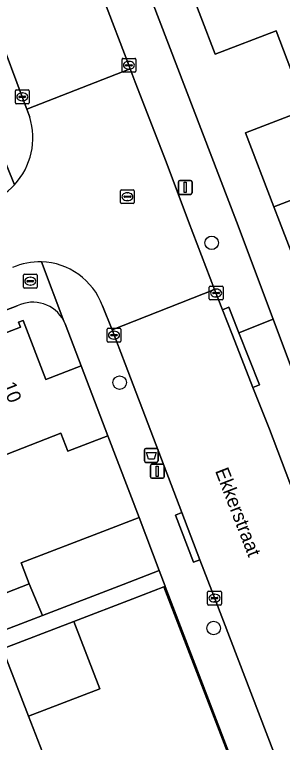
# Model space of a CAD drawing. Extents: x 159262 to 160143, y 383399 to 384319.
# Drawn here: x 159474.9 to 159494.3, y 383712.3 to 383765 of the extents above; entities that cross this region are included whole.
import ezdxf

# ---------------------------------------------------------------- set-up
doc = ezdxf.new("R2010")
doc.units = 0
for name, color, linetype in [('IMGEO_Afvalbak', 7, 'Continuous'), ('IMGEO_Boom', 7, 'Continuous'), ('IMGEO_Brandkraan', 7, 'Continuous'), ('IMGEO_Erf', 7, 'Continuous'), ('IMGEO_Kolk', 7, 'Continuous'), ('IMGEO_Lichtmast', 7, 'Continuous'), ('IMGEO_Muur', 7, 'Continuous'), ('IMGEO_Openbare_ruimte_label', 7, 'Continuous'), ('IMGEO_Pand', 7, 'Continuous'), ('IMGEO_Pand_nummerreeks', 7, 'Continuous'), ('IMGEO_Rijbaan_lokaal_gesloten', 7, 'Continuous'), ('IMGEO_Rijbaan_lokaal_open', 7, 'Continuous'), ('IMGEO_Rioolput', 7, 'Continuous'), ('IMGEO_Voetpad_open', 7, 'Continuous')]:
    doc.layers.add(name, color=color, linetype=linetype)

msp = doc.modelspace()

# ---------------------------------------------------------------- linework, layer by layer
at = {"layer": 'IMGEO_Afvalbak'}
for p, q in [((159484.342, 383732.689), (159484.342, 383733.489)), ((159484.342, 383733.489), (159484.342, 383732.689)), ((159484.442, 383733.589), (159485.232, 383733.589)), ((159485.232, 383733.589), (159484.442, 383733.589)), ((159485.332, 383733.489), (159485.332, 383732.689)), ((159485.332, 383732.689), (159485.332, 383733.489)), ((159485.232, 383732.589), (159484.442, 383732.589)), ((159484.442, 383732.589), (159485.232, 383732.589))]:
    msp.add_line(p, q, dxfattribs=at)
msp.add_lwpolyline([(159484.485, 383733.303), (159485.189, 383733.303), (159485.04, 383732.833), (159484.634, 383732.833), (159484.485, 383733.303)], dxfattribs=at)
for centre, start, end in [((159484.442, 383733.489), 90, 180), ((159484.442, 383733.489), 90, 180), ((159485.232, 383733.489), 0, 90), ((159485.232, 383733.489), 360, 90), ((159484.442, 383732.689), 180, 270), ((159484.442, 383732.689), 180, 270), ((159485.232, 383732.689), 270, 0), ((159485.232, 383732.689), 270, 0)]:
    msp.add_arc(centre, 0.1, start, end, dxfattribs=at)
at = {"layer": 'IMGEO_Boom'}
for centre in [(159489.216, 383748.468), (159482.553, 383738.358), (159489.356, 383720.608)]:
    msp.add_circle(centre, 0.489, dxfattribs=at)
at = {"layer": 'IMGEO_Brandkraan'}
for p, q in [((159475.58, 383745.266), (159475.58, 383746.118)), ((159475.655, 383746.192), (159476.507, 383746.192)), ((159476.581, 383746.118), (159476.581, 383745.266)), ((159475.839, 383745.686), (159475.839, 383745.698)), ((159476.277, 383745.649), (159475.879, 383745.649)), ((159475.882, 383745.735), (159476.28, 383745.735)), ((159476.068, 383745.972), (159476.093, 383745.972)), ((159476.323, 383745.698), (159476.323, 383745.686)), ((159476.507, 383745.192), (159475.655, 383745.192)), ((159476.091, 383745.412), (159476.066, 383745.412))]:
    msp.add_line(p, q, dxfattribs=at)
for points in [[(159475.58, 383745.266), (159475.58, 383746.118)], [(159475.655, 383746.192), (159476.507, 383746.192)], [(159476.581, 383746.118), (159476.581, 383745.266)], [(159476.507, 383745.192), (159475.655, 383745.192)]]:
    msp.add_lwpolyline(points, dxfattribs=at)
for centre, radius, start, end in [((159475.657, 383746.116), 0.0765, 91.552, 178.448), ((159475.657, 383746.116), 0.0765, 91.552, 178.448), ((159476.505, 383746.116), 0.0765, 1.552, 88.448), ((159476.505, 383746.116), 0.0765, 1.552, 88.448), ((159475.879, 383745.695), 0.0403, 85.8775, 175.7526), ((159475.876, 383745.685), 0.0366, 178.938, 274.7102), ((159476.28, 383745.692), 0.043, 264.8664, 352.4533), ((159476.284, 383745.697), 0.0386, 1.7309, 96.639), ((159475.657, 383745.268), 0.0765, 181.552, 268.448), ((159475.657, 383745.268), 0.0765, 181.552, 268.448), ((159476.505, 383745.268), 0.0765, 271.552, 358.448), ((159476.505, 383745.268), 0.0765, 271.552, 358.448)]:
    msp.add_arc(centre, radius, start, end, dxfattribs=at)
for centre, major_axis, ratio, start_param, end_param in [((159476.067, 383745.692), (-0.387, 0.002), 0.722429, 4.712389, 7.853982), ((159476.092, 383745.692), (-0.39, 0.002), 0.717154, 1.570796, 4.712389)]:
    msp.add_ellipse(centre, major_axis=major_axis, ratio=ratio, start_param=start_param, end_param=end_param, dxfattribs=at)
at = {"layer": 'IMGEO_Erf'}
for points in [[(159458.43, 383834.836), (159491.014, 383750), (159493.662, 383742.956), (159500, 383726.102), (159501.344, 383722.528)], [(159494.951, 383761.005), (159493.876, 383763.807), (159489.475, 383762.119), (159487.395, 383767.541)], [(159495.782, 383745.687), (159494.127, 383750), (159493.714, 383751.078), (159491.668, 383756.411), (159496.067, 383758.098)], [(159475.133, 383743.901), (159411.208, 383719.553), (159411.043, 383719.484)], [(159469.956, 383740.291), (159475.364, 383742.37), (159475.224, 383742.733), (159475.556, 383742.861), (159477.2, 383738.588), (159479.759, 383739.576), (159478.603, 383742.601), (159478.507, 383742.809)], [(159472.095, 383722.294), (159476.006, 383723.798), (159475.423, 383725.318), (159481.33, 383727.59), (159483.955, 383728.599), (159481.692, 383734.52), (159478.794, 383733.402), (159478.299, 383734.69), (159472.711, 383732.544)], [(159493.36, 383704.052), (159485.859, 383723.61), (159485.853, 383723.626), (159485.763, 383723.591), (159491.137, 383709.634)]]:
    msp.add_lwpolyline(points, dxfattribs=at)
msp.add_lwpolyline([(159481.112, 383716.217), (159479.244, 383721.092), (159474.079, 383719.112), (159475.962, 383714.243)], close=True, dxfattribs=at)
msp.add_arc((159476.27, 383741.654), 2.518, 27.3001, 116.8314, dxfattribs=at)
at = {"layer": 'IMGEO_Kolk'}
for p, q in [((159482.723, 383760.881), (159482.723, 383761.733)), ((159482.798, 383761.807), (159483.65, 383761.807)), ((159482.982, 383761.301), (159482.982, 383761.313)), ((159483.025, 383761.35), (159483.423, 383761.35)), ((159483.211, 383761.587), (159483.236, 383761.587)), ((159483.466, 383761.313), (159483.466, 383761.301)), ((159483.724, 383761.733), (159483.724, 383760.881)), ((159483.65, 383760.807), (159482.798, 383760.807)), ((159483.42, 383761.264), (159483.022, 383761.264)), ((159483.234, 383761.027), (159483.209, 383761.027)), ((159474.998, 383758.597), (159474.998, 383759.449)), ((159475.073, 383759.523), (159475.925, 383759.523)), ((159475.486, 383759.303), (159475.511, 383759.303)), ((159475.999, 383759.449), (159475.999, 383758.597)), ((159475.257, 383759.017), (159475.257, 383759.029)), ((159475.695, 383758.98), (159475.297, 383758.98)), ((159475.3, 383759.066), (159475.698, 383759.066)), ((159475.509, 383758.743), (159475.484, 383758.743)), ((159475.741, 383759.029), (159475.741, 383759.017)), ((159475.925, 383758.523), (159475.073, 383758.523)), ((159489.038, 383744.409), (159489.038, 383745.261)), ((159489.113, 383745.335), (159489.965, 383745.335)), ((159489.526, 383745.115), (159489.551, 383745.115)), ((159490.039, 383745.261), (159490.039, 383744.409)), ((159489.297, 383744.829), (159489.297, 383744.841)), ((159489.735, 383744.792), (159489.337, 383744.792)), ((159489.34, 383744.878), (159489.738, 383744.878)), ((159489.549, 383744.555), (159489.524, 383744.555)), ((159489.781, 383744.841), (159489.781, 383744.829)), ((159489.965, 383744.335), (159489.113, 383744.335)), ((159481.642, 383741.362), (159481.642, 383742.214)), ((159481.717, 383742.288), (159482.569, 383742.288)), ((159481.944, 383741.831), (159482.342, 383741.831)), ((159482.13, 383742.068), (159482.155, 383742.068)), ((159482.643, 383742.214), (159482.643, 383741.362)), ((159481.901, 383741.782), (159481.901, 383741.794)), ((159482.339, 383741.745), (159481.941, 383741.745)), ((159482.153, 383741.508), (159482.128, 383741.508)), ((159482.385, 383741.794), (159482.385, 383741.782)), ((159482.569, 383741.288), (159481.717, 383741.288)), ((159488.922, 383722.348), (159488.922, 383723.2)), ((159488.997, 383723.274), (159489.849, 383723.274)), ((159489.41, 383723.054), (159489.435, 383723.054)), ((159489.923, 383723.2), (159489.923, 383722.348)), ((159489.181, 383722.768), (159489.181, 383722.78)), ((159489.619, 383722.731), (159489.221, 383722.731)), ((159489.224, 383722.817), (159489.622, 383722.817)), ((159489.433, 383722.494), (159489.408, 383722.494)), ((159489.665, 383722.78), (159489.665, 383722.768)), ((159489.849, 383722.274), (159488.997, 383722.274))]:
    msp.add_line(p, q, dxfattribs=at)
for points in [[(159482.723, 383760.881), (159482.723, 383761.733)], [(159482.798, 383761.807), (159483.65, 383761.807)], [(159483.724, 383761.733), (159483.724, 383760.881)], [(159483.65, 383760.807), (159482.798, 383760.807)], [(159474.998, 383758.597), (159474.998, 383759.449)], [(159475.073, 383759.523), (159475.925, 383759.523)], [(159475.999, 383759.449), (159475.999, 383758.597)], [(159475.925, 383758.523), (159475.073, 383758.523)], [(159489.038, 383744.409), (159489.038, 383745.261)], [(159489.113, 383745.335), (159489.965, 383745.335)], [(159490.039, 383745.261), (159490.039, 383744.409)], [(159489.965, 383744.335), (159489.113, 383744.335)], [(159481.642, 383741.362), (159481.642, 383742.214)], [(159481.717, 383742.288), (159482.569, 383742.288)], [(159482.643, 383742.214), (159482.643, 383741.362)], [(159482.569, 383741.288), (159481.717, 383741.288)], [(159488.922, 383722.348), (159488.922, 383723.2)], [(159488.997, 383723.274), (159489.849, 383723.274)], [(159489.923, 383723.2), (159489.923, 383722.348)], [(159489.849, 383722.274), (159488.997, 383722.274)]]:
    msp.add_lwpolyline(points, dxfattribs=at)
for centre, radius, start, end in [((159482.8, 383761.731), 0.0765, 91.552, 178.448), ((159482.8, 383761.731), 0.0765, 91.552, 178.448), ((159483.022, 383761.31), 0.0403, 85.8775, 175.7526), ((159483.019, 383761.3), 0.0366, 178.938, 274.7102), ((159483.423, 383761.307), 0.043, 264.8664, 352.4533), ((159483.427, 383761.312), 0.0386, 1.7309, 96.639), ((159483.648, 383761.731), 0.0765, 1.552, 88.448), ((159483.648, 383761.731), 0.0765, 1.552, 88.448), ((159482.8, 383760.883), 0.0765, 181.552, 268.448), ((159482.8, 383760.883), 0.0765, 181.552, 268.448), ((159483.648, 383760.883), 0.0765, 271.552, 358.448), ((159483.648, 383760.883), 0.0765, 271.552, 358.448), ((159475.075, 383759.447), 0.0765, 91.552, 178.448), ((159475.075, 383759.447), 0.0765, 91.552, 178.448), ((159475.923, 383759.447), 0.0765, 1.552, 88.448), ((159475.923, 383759.447), 0.0765, 1.552, 88.448), ((159475.297, 383759.026), 0.0403, 85.8775, 175.7526), ((159475.294, 383759.016), 0.0366, 178.938, 274.7102), ((159475.698, 383759.023), 0.043, 264.8664, 352.4533), ((159475.702, 383759.028), 0.0386, 1.7309, 96.639), ((159475.075, 383758.599), 0.0765, 181.552, 268.448), ((159475.075, 383758.599), 0.0765, 181.552, 268.448), ((159475.923, 383758.599), 0.0765, 271.552, 358.448), ((159475.923, 383758.599), 0.0765, 271.552, 358.448), ((159489.115, 383745.259), 0.0765, 91.552, 178.448), ((159489.115, 383745.259), 0.0765, 91.552, 178.448), ((159489.963, 383745.259), 0.0765, 1.552, 88.448), ((159489.963, 383745.259), 0.0765, 1.552, 88.448), ((159489.337, 383744.838), 0.0403, 85.8775, 175.7526), ((159489.334, 383744.828), 0.0366, 178.938, 274.7102), ((159489.738, 383744.835), 0.043, 264.8664, 352.4533), ((159489.742, 383744.84), 0.0386, 1.7309, 96.639), ((159489.115, 383744.411), 0.0765, 181.552, 268.448), ((159489.115, 383744.411), 0.0765, 181.552, 268.448), ((159489.963, 383744.411), 0.0765, 271.552, 358.448), ((159489.963, 383744.411), 0.0765, 271.552, 358.448), ((159481.719, 383742.212), 0.0765, 91.552, 178.448), ((159481.719, 383742.212), 0.0765, 91.552, 178.448), ((159481.941, 383741.791), 0.0403, 85.8775, 175.7526), ((159482.346, 383741.793), 0.0386, 1.7309, 96.639), ((159482.567, 383742.212), 0.0765, 1.552, 88.448), ((159482.567, 383742.212), 0.0765, 1.552, 88.448), ((159481.719, 383741.364), 0.0765, 181.552, 268.448), ((159481.719, 383741.364), 0.0765, 181.552, 268.448), ((159481.938, 383741.781), 0.0366, 178.938, 274.7102), ((159482.342, 383741.788), 0.043, 264.8664, 352.4533), ((159482.567, 383741.364), 0.0765, 271.552, 358.448), ((159482.567, 383741.364), 0.0765, 271.552, 358.448), ((159488.999, 383723.198), 0.0765, 91.552, 178.448), ((159488.999, 383723.198), 0.0765, 91.552, 178.448), ((159489.847, 383723.198), 0.0765, 1.552, 88.448), ((159489.847, 383723.198), 0.0765, 1.552, 88.448), ((159489.221, 383722.777), 0.0403, 85.8775, 175.7526), ((159489.218, 383722.767), 0.0366, 178.938, 274.7102), ((159489.622, 383722.774), 0.043, 264.8664, 352.4533), ((159489.626, 383722.779), 0.0386, 1.7309, 96.639), ((159488.999, 383722.35), 0.0765, 181.552, 268.448), ((159488.999, 383722.35), 0.0765, 181.552, 268.448), ((159489.847, 383722.35), 0.0765, 271.552, 358.448), ((159489.847, 383722.35), 0.0765, 271.552, 358.448)]:
    msp.add_arc(centre, radius, start, end, dxfattribs=at)
for centre, major_axis, ratio, start_param, end_param in [((159483.21, 383761.307), (-0.387, 0.002), 0.722429, 4.712389, 7.853982), ((159483.235, 383761.307), (-0.39, 0.002), 0.717154, 1.570796, 4.712389), ((159475.485, 383759.023), (-0.387, 0.002), 0.722429, 4.712389, 7.853982), ((159475.51, 383759.023), (-0.39, 0.002), 0.717154, 1.570796, 4.712389), ((159489.525, 383744.835), (-0.387, 0.002), 0.722429, 4.712389, 7.853982), ((159489.55, 383744.835), (-0.39, 0.002), 0.717154, 1.570796, 4.712389), ((159482.129, 383741.788), (-0.387, 0.002), 0.722429, 4.712389, 7.853982), ((159482.154, 383741.788), (-0.39, 0.002), 0.717154, 1.570796, 4.712389), ((159489.409, 383722.774), (-0.387, 0.002), 0.722429, 4.712389, 7.853982), ((159489.434, 383722.774), (-0.39, 0.002), 0.717154, 1.570796, 4.712389)]:
    msp.add_ellipse(centre, major_axis=major_axis, ratio=ratio, start_param=start_param, end_param=end_param, dxfattribs=at)
at = {"layer": 'IMGEO_Lichtmast'}
for p, q in [((159486.904, 383752.97), (159487.694, 383752.97)), ((159487.694, 383752.97), (159486.904, 383752.97)), ((159486.804, 383752.07), (159486.804, 383752.87)), ((159486.804, 383752.87), (159486.804, 383752.07)), ((159487.794, 383752.87), (159487.794, 383752.07)), ((159487.794, 383752.07), (159487.794, 383752.87)), ((159487.694, 383751.97), (159486.904, 383751.97)), ((159486.904, 383751.97), (159487.694, 383751.97)), ((159484.882, 383732.449), (159485.672, 383732.449)), ((159485.672, 383732.449), (159484.882, 383732.449)), ((159484.782, 383731.549), (159484.782, 383732.349)), ((159484.782, 383732.349), (159484.782, 383731.549)), ((159485.772, 383732.349), (159485.772, 383731.549)), ((159485.772, 383731.549), (159485.772, 383732.349)), ((159485.672, 383731.449), (159484.882, 383731.449)), ((159484.882, 383731.449), (159485.672, 383731.449))]:
    msp.add_line(p, q, dxfattribs=at)
for points in [[(159487.224, 383752.845), (159487.374, 383752.845), (159487.374, 383752.095), (159487.224, 383752.095), (159487.224, 383752.845)], [(159485.202, 383732.324), (159485.352, 383732.324), (159485.352, 383731.574), (159485.202, 383731.574), (159485.202, 383732.324)]]:
    msp.add_lwpolyline(points, dxfattribs=at)
for centre, start, end in [((159486.904, 383752.87), 90, 180), ((159486.904, 383752.87), 90, 180), ((159487.694, 383752.87), 0, 90), ((159487.694, 383752.87), 360, 90), ((159486.904, 383752.07), 180, 270), ((159486.904, 383752.07), 180, 270), ((159487.694, 383752.07), 270, 0), ((159487.694, 383752.07), 270, 0), ((159484.882, 383732.349), 90, 180), ((159484.882, 383732.349), 90, 180), ((159485.672, 383732.349), 0, 90), ((159485.672, 383732.349), 360, 90), ((159484.882, 383731.549), 180, 270), ((159484.882, 383731.549), 180, 270), ((159485.672, 383731.549), 270, 0), ((159485.672, 383731.549), 270, 0)]:
    msp.add_arc(centre, 0.1, start, end, dxfattribs=at)
at = {"layer": 'IMGEO_Muur'}
msp.add_lwpolyline([(159481.692, 383734.52), (159483.955, 383728.599)], dxfattribs=at)
at = {"layer": 'IMGEO_Pand'}
for points in [[(159494.951, 383761.005), (159500, 383762.933), (159500.424, 383763.095), (159500, 383764.214), (159499.277, 383766.124), (159497.269, 383771.357), (159487.395, 383767.541), (159489.475, 383762.119), (159493.876, 383763.807)], [(159500.424, 383763.095), (159500, 383762.933), (159494.951, 383761.005), (159496.067, 383758.098), (159491.668, 383756.411), (159493.714, 383751.078), (159500, 383753.487), (159502.011, 383754.257), (159506.656, 383756.036), (159503.527, 383764.28)], [(159508.35, 383747.25), (159507.305, 383750), (159507.161, 383750.38), (159506.16, 383750), (159503.945, 383749.159), (159503.626, 383750), (159502.011, 383754.257), (159500, 383753.487), (159493.714, 383751.078), (159494.127, 383750), (159495.782, 383745.687), (159500, 383747.318), (159501.768, 383748.001), (159502.855, 383745.139)], [(159472.711, 383732.544), (159478.299, 383734.69), (159478.794, 383733.402), (159481.692, 383734.52), (159479.759, 383739.576), (159477.2, 383738.588), (159475.556, 383742.861), (159475.224, 383742.733), (159475.364, 383742.37), (159469.956, 383740.291), (159469.817, 383740.655), (159469.621, 383740.58)], [(159476.006, 383723.798), (159476.954, 383721.516), (159482.801, 383723.764), (159485.418, 383724.77), (159483.955, 383728.599), (159481.33, 383727.59), (159475.423, 383725.318)], [(159476.006, 383723.798), (159472.095, 383722.294), (159472.929, 383720.123), (159472.981, 383719.988), (159476.954, 383721.516)], [(159485.763, 383723.591), (159483.511, 383722.728), (159479.244, 383721.092), (159481.112, 383716.217), (159475.962, 383714.243), (159477.308, 383710.765), (159479.649, 383704.714), (159479.829, 383704.783), (159482.376, 383705.767), (159482.797, 383704.653), (159484.759, 383705.406), (159485.114, 383704.464), (159484.913, 383704.379), (159485.036, 383704.069), (159489.964, 383705.968), (159488.886, 383708.768), (159491.137, 383709.634)], [(159477.308, 383710.765), (159475.962, 383714.243), (159474.079, 383719.112), (159470, 383717.549), (159472.05, 383712.2), (159466.909, 383710.231), (159468.071, 383707.226), (159470.415, 383701.164), (159470.589, 383701.232), (159473.152, 383702.227), (159473.568, 383701.107), (159475.541, 383701.86), (159475.896, 383700.918), (159475.695, 383700.833), (159475.818, 383700.523), (159480.562, 383702.355), (159479.649, 383704.714)]]:
    msp.add_lwpolyline(points, close=True, dxfattribs=at)
at = {"layer": 'IMGEO_Rijbaan_lokaal_gesloten'}
msp.add_lwpolyline([(159483.308, 383761.046), (159483.224, 383761.306), (159479.585, 383770.783), (159477.396, 383776.499), (159473.023, 383787.916), (159471.145, 383792.82), (159467.126, 383803.315), (159464.68, 383809.703), (159460.676, 383820.157), (159458.217, 383826.578), (159457.134, 383829.395), (159449.663, 383826.529), (159449.79, 383826.168), (159450.958, 383823.16), (159466.558, 383782.495), (159469.529, 383774.749), (159472.225, 383767.721), (159475.5, 383759.023), (159475.831, 383758.13)], close=True, dxfattribs=at)
msp.add_lwpolyline([(159518.009, 383670.645), (159500.962, 383715.104), (159500, 383717.631), (159498.316, 383722.058), (159497.711, 383723.646), (159496.348, 383727.229), (159493.397, 383734.979), (159492.205, 383738.007), (159490.718, 383741.784), (159489.992, 383743.627), (159489.424, 383745.092), (159482.013, 383742.165), (159482.959, 383739.704), (159487.06, 383728.953), (159488.361, 383725.542), (159489.512, 383722.543), (159495.821, 383706.144)], dxfattribs=at)
at = {"layer": 'IMGEO_Rijbaan_lokaal_open'}
for points in [[(159485.92, 383754.33), (159483.68, 383760.076), (159483.308, 383761.046), (159475.831, 383758.13), (159476.042, 383757.553)], [(159481.306, 383743.909), (159482.013, 383742.165), (159489.424, 383745.092), (159487.543, 383750), (159485.92, 383754.33)]]:
    msp.add_lwpolyline(points, dxfattribs=at)
for centre, radius, start, end in [((159471.279, 383756.063), 4.99, 317.1884, 17.3665), ((159471.28, 383756.055), 4.984, 288.3378, 317.2544), ((159476.758, 383742.279), 4.811, 88.4427, 113.9657), ((159476.764, 383742.257), 4.833, 19.992, 88.5214)]:
    msp.add_arc(centre, radius, start, end, dxfattribs=at)
at = {"layer": 'IMGEO_Rioolput'}
for p, q in [((159482.611, 383751.375), (159482.611, 383752.227)), ((159482.686, 383752.301), (159483.538, 383752.301)), ((159482.913, 383751.844), (159483.311, 383751.844)), ((159483.099, 383752.081), (159483.124, 383752.081)), ((159483.612, 383752.227), (159483.612, 383751.375)), ((159483.538, 383751.301), (159482.686, 383751.301)), ((159482.87, 383751.795), (159482.87, 383751.807)), ((159483.308, 383751.758), (159482.91, 383751.758)), ((159483.122, 383751.521), (159483.097, 383751.521)), ((159483.354, 383751.807), (159483.354, 383751.795))]:
    msp.add_line(p, q, dxfattribs=at)
for points in [[(159482.611, 383751.375), (159482.611, 383752.227)], [(159482.686, 383752.301), (159483.538, 383752.301)], [(159483.612, 383752.227), (159483.612, 383751.375)], [(159483.538, 383751.301), (159482.686, 383751.301)]]:
    msp.add_lwpolyline(points, dxfattribs=at)
for centre, radius, start, end in [((159482.688, 383752.225), 0.0765, 91.552, 178.448), ((159482.688, 383752.225), 0.0765, 91.552, 178.448), ((159482.91, 383751.804), 0.0403, 85.8775, 175.7526), ((159483.315, 383751.806), 0.0386, 1.7309, 96.639), ((159483.536, 383752.225), 0.0765, 1.552, 88.448), ((159483.536, 383752.225), 0.0765, 1.552, 88.448), ((159482.688, 383751.377), 0.0765, 181.552, 268.448), ((159482.688, 383751.377), 0.0765, 181.552, 268.448), ((159482.907, 383751.794), 0.0366, 178.938, 274.7102), ((159483.311, 383751.801), 0.043, 264.8664, 352.4533), ((159483.536, 383751.377), 0.0765, 271.552, 358.448), ((159483.536, 383751.377), 0.0765, 271.552, 358.448)]:
    msp.add_arc(centre, radius, start, end, dxfattribs=at)
for centre, major_axis, ratio, start_param, end_param in [((159483.098, 383751.801), (-0.387, 0.002), 0.722429, 4.712389, 7.853982), ((159483.123, 383751.801), (-0.39, 0.002), 0.717154, 1.570796, 4.712389)]:
    msp.add_ellipse(centre, major_axis=major_axis, ratio=ratio, start_param=start_param, end_param=end_param, dxfattribs=at)
at = {"layer": 'IMGEO_Voetpad_open'}
for points in [[(159479.585, 383770.783), (159483.224, 383761.306), (159483.308, 383761.046), (159483.68, 383760.076), (159485.92, 383754.33), (159487.543, 383750), (159489.424, 383745.092), (159489.992, 383743.627), (159490.457, 383743.81), (159491.182, 383741.969), (159493.662, 383742.956), (159491.014, 383750), (159458.43, 383834.836)], [(159476.042, 383757.553), (159475.831, 383758.13), (159475.5, 383759.023), (159472.225, 383767.721), (159469.529, 383774.749), (159469.063, 383774.57), (159466.092, 383782.316), (159466.558, 383782.495), (159450.958, 383823.16)], [(159458.728, 383794.536), (159460.444, 383789.972), (159461.207, 383787.944), (159463.444, 383781.995), (159464.928, 383778.147), (159465.456, 383776.746), (159466.884, 383773.04), (159469.357, 383766.588), (159469.512, 383766.187), (159469.412, 383766.15), (159471.332, 383761.42), (159472.73, 383758.03), (159474.94, 383752.672)], [(159474.94, 383752.672), (159472.73, 383758.03)], [(159476.889, 383747.088), (159478.507, 383742.809), (159478.603, 383742.601), (159479.759, 383739.576), (159481.692, 383734.52), (159483.955, 383728.599), (159485.418, 383724.77), (159485.853, 383723.626), (159485.859, 383723.61), (159493.36, 383704.052), (159494.814, 383700.262), (159496.449, 383695.986), (159500, 383686.749), (159513.499, 383651.634)], [(159478.507, 383742.809), (159476.889, 383747.088)], [(159407.009, 383717.814), (159411.043, 383719.484), (159411.208, 383719.553), (159475.133, 383743.901)], [(159500.226, 383694.637), (159499.256, 383694.263), (159495.247, 383704.671), (159496.217, 383705.045), (159495.821, 383706.144), (159489.512, 383722.543), (159488.361, 383725.542), (159487.894, 383725.364), (159486.593, 383728.775), (159487.06, 383728.953), (159482.959, 383739.704), (159482.013, 383742.165), (159481.306, 383743.909)], [(159493.662, 383742.956), (159491.182, 383741.969), (159492.67, 383738.19), (159492.205, 383738.007), (159493.397, 383734.979), (159496.348, 383727.229), (159496.815, 383727.407), (159498.178, 383723.824), (159497.711, 383723.646), (159498.316, 383722.058), (159499.288, 383722.428), (159501.934, 383715.474), (159500.962, 383715.104), (159518.009, 383670.645)], [(159521.968, 383664.836), (159523.427, 383665.372), (159523.264, 383665.799), (159522.704, 383667.239), (159512.811, 383692.674), (159509.321, 383701.658), (159506.408, 383709.106), (159505.749, 383710.795), (159503.698, 383716.375), (159503.16, 383717.83), (159501.344, 383722.528), (159500, 383726.102), (159493.662, 383742.956)], [(159455.588, 383712.026), (159460.746, 383714.002), (159464.844, 383715.573), (159470, 383717.549), (159474.079, 383719.112), (159479.244, 383721.092), (159483.511, 383722.728), (159485.763, 383723.591), (159485.853, 383723.626), (159485.418, 383724.77), (159482.801, 383723.764), (159476.954, 383721.516), (159472.981, 383719.988), (159472.929, 383720.123), (159469.08, 383718.649), (159465.394, 383717.243), (159459.529, 383715.005), (159457.483, 383714.225), (159453.776, 383712.81), (159449.626, 383711.226)]]:
    msp.add_lwpolyline(points, dxfattribs=at)
for points in [[(159492.205, 383738.007), (159492.67, 383738.19), (159491.182, 383741.969), (159490.457, 383743.81), (159489.992, 383743.627), (159490.718, 383741.784)], [(159487.06, 383728.953), (159486.593, 383728.775), (159487.894, 383725.364), (159488.361, 383725.542)]]:
    msp.add_lwpolyline(points, close=True, dxfattribs=at)
for centre, radius, start, end in [((159471.279, 383756.063), 4.99, 317.1884, 17.3665), ((159471.28, 383756.055), 4.984, 288.3378, 317.2544), ((159476.758, 383742.279), 4.811, 88.4427, 113.9657), ((159476.764, 383742.257), 4.833, 19.992, 88.5214), ((159476.27, 383741.654), 2.518, 27.3001, 116.8314)]:
    msp.add_arc(centre, radius, start, end, dxfattribs=at)

# ---------------------------------------------------------------- texts
at = {"layer": 'IMGEO_Openbare_ruimte_label'}
msp.add_text('Ekkerstraat', height=1, rotation=291.2268, dxfattribs=at).set_placement((159489.447, 383731.977))
at = {"layer": 'IMGEO_Pand_nummerreeks'}
msp.add_text('10', height=1, rotation=291.0438, dxfattribs=at).set_placement((159474.023, 383738.193))

doc.saveas('drawing.dxf')
